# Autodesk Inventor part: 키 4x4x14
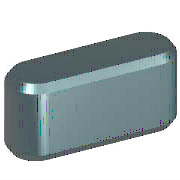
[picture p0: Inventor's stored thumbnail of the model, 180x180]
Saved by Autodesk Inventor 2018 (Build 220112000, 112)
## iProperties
IsCustomPart: 1
Created: 2012-02
Part Number: 키 4x4x14
Material: 강철, 연강
Description: 키 및 해당 키홈
Document SubType Name: Modeling
Standard: KS B 1311
Designer: mduedu
Standards Organization: KS
Language: ko-KR
Size Designation: 4 x 4 x 14
Categories: <MemberInstance><Categories><Category DisplayName="샤프트 부품" InternalName="7f7aeb1f-a693-4053-b835-cee3144e0d98" Mnemonic="SHFT"><Category DisplayName="키" Interna
Density: 1 g/cm^3
Appearance: 노란색
Author: mduedu
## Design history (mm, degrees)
workplane "Work Plane1"
workplane "Work Plane2"
sketch "스케치1"
  geometry: L1 (2, 2)-(12, 2); L2 (12, -2)-(2, -2); L3 (0, 9.4)-(0, -7.4) reference; L4 (-5, 0)-(30, 0) reference; L5 (14, 0)-(14, 7); A1 r 2 centre (2, 0) between (2, 2) and (2, -2); A2 r 2 centre (12, 0) between (12, -2) and (12, 2)
  constraints: 6 end point, 5 point on circle, 4 tangent, 3 point on line, 2 centre point, 1 horizontal, 1 parallel, 1 perpendicular
  dimensions: "d0" = 2 radius of A1 (= 0.5 x PB); "d13" = 2 radius of A2 (= 0.5 x PB); "d14" = 14 distance between parallel lines of L5 L3 (= NLG)
extrude "본체1" new body sketch "스케치1" taper "d3" = 0 deg; stored distance "d4" = 10
workplane "Work Plane3"
body "Solid1"
chamfer "모따기1" distance "d8" = 0.25 (= PHH); stored, may be unused: second distance "d9" = 0.25 (= PHH), angle "d15" = 45 deg
other parameters: "d1" = -2.5 (= -PNT), "d2" = 1.5 (= PH - PNT), "NLG" = 14 [user parameter; used in 3 equation terms], "PB" = 4 [user parameter; used in 2 equation terms], "PNT" = 2.5 [user parameter; used in 2 equation terms], "PH" = 4 [user parameter; used in 1 equation term], "PHH" = 0.25 [user parameter; used in 2 equation terms], "d10" = 0, "d16" = 0, "d17" = 0, "d18" = 0, "PLB2" = 14 (= NLG) [user parameter], "WDMAX" = 12 [user parameter], "PLB1" = 14 (= NLG) [user parameter], "RR" = 0.08 [user parameter], "PUEB" = 1.8 [user parameter]
